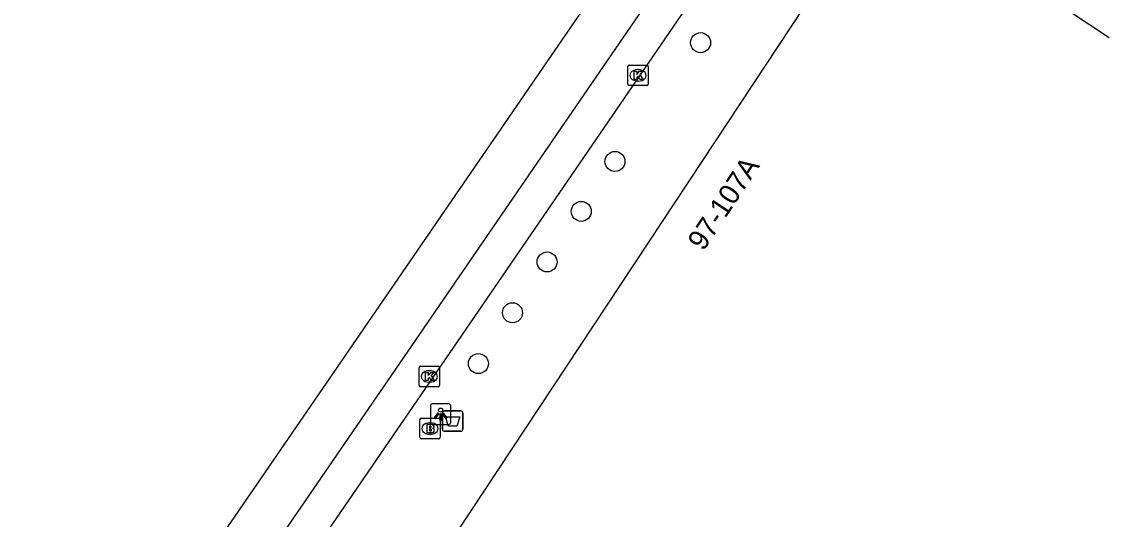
# Model space of a CAD drawing. Extents: x 160356 to 161355, y 381727 to 382845.
# Drawn here: x 160764.7 to 160817.9, y 382583 to 382607.3 of the extents above; entities that cross this region are included whole.
import ezdxf

# ---------------------------------------------------------------- set-up
doc = ezdxf.new("R2010")
doc.units = 0
for name, color, linetype in [('IMGEO_Afvalbak', 7, 'Continuous'), ('IMGEO_Boom', 7, 'Continuous'), ('IMGEO_Brandkraan', 7, 'Continuous'), ('IMGEO_Kolk', 7, 'Continuous'), ('IMGEO_Lichtpunt', 7, 'Continuous'), ('IMGEO_Pand', 7, 'Continuous'), ('IMGEO_Pand_nummerreeks', 7, 'Continuous'), ('IMGEO_Rijbaan_lokaal_gesloten', 7, 'Continuous')]:
    doc.layers.add(name, color=color, linetype=linetype)

msp = doc.modelspace()

# ---------------------------------------------------------------- linework, layer by layer
at = {"layer": 'IMGEO_Afvalbak'}
for p, q in [((160785.325, 382587.366), (160785.325, 382588.166)), ((160785.325, 382588.166), (160785.325, 382587.366)), ((160785.425, 382588.266), (160786.215, 382588.266)), ((160786.215, 382588.266), (160785.425, 382588.266)), ((160786.315, 382588.166), (160786.315, 382587.366)), ((160786.315, 382587.366), (160786.315, 382588.166)), ((160786.215, 382587.266), (160785.425, 382587.266)), ((160785.425, 382587.266), (160786.215, 382587.266))]:
    msp.add_line(p, q, dxfattribs=at)
msp.add_lwpolyline([(160785.468, 382587.98), (160786.172, 382587.98), (160786.023, 382587.51), (160785.617, 382587.51), (160785.468, 382587.98)], dxfattribs=at)
for centre, start, end in [((160785.425, 382588.166), 90, 180), ((160785.425, 382588.166), 90, 180), ((160786.215, 382588.166), 0, 90), ((160786.215, 382588.166), 360, 90), ((160785.425, 382587.366), 180, 270), ((160785.425, 382587.366), 180, 270), ((160786.215, 382587.366), 270, 0), ((160786.215, 382587.366), 270, 0)]:
    msp.add_arc(centre, 0.1, start, end, dxfattribs=at)
at = {"layer": 'IMGEO_Boom'}
for centre in [(160797.947, 382606.26), (160793.762, 382600.455), (160792.113, 382598.016), (160790.44, 382595.542), (160788.749, 382593.06), (160787.081, 382590.575)]:
    msp.add_circle(centre, 0.489, dxfattribs=at)
at = {"layer": 'IMGEO_Brandkraan'}
for p, q in [((160784.214, 382586.975), (160784.214, 382587.827)), ((160784.289, 382587.901), (160785.141, 382587.901)), ((160785.215, 382587.827), (160785.215, 382586.975)), ((160784.702, 382587.681), (160784.727, 382587.681)), ((160785.141, 382586.901), (160784.289, 382586.901)), ((160784.725, 382587.121), (160784.7, 382587.121))]:
    msp.add_line(p, q, dxfattribs=at)
for points in [[(160784.214, 382586.975), (160784.214, 382587.827)], [(160784.289, 382587.901), (160785.141, 382587.901)], [(160785.215, 382587.827), (160785.215, 382586.975)], [(160784.562, 382587.601), (160784.562, 382587.201), (160784.775, 382587.201)], [(160784.793, 382587.601), (160784.562, 382587.601)], [(160784.741, 382587.52), (160784.687, 382587.52), (160784.687, 382587.444)], [(160784.687, 382587.444), (160784.74, 382587.444)], [(160784.749, 382587.368), (160784.687, 382587.368), (160784.687, 382587.287)], [(160784.687, 382587.287), (160784.749, 382587.287)], [(160785.141, 382586.901), (160784.289, 382586.901)]]:
    msp.add_lwpolyline(points, dxfattribs=at)
for centre, radius, start, end in [((160784.291, 382587.825), 0.0765, 91.552, 178.448), ((160784.291, 382587.825), 0.0765, 91.552, 178.448), ((160785.139, 382587.825), 0.0765, 1.552, 88.448), ((160785.139, 382587.825), 0.0765, 1.552, 88.448), ((160784.742, 382587.482), 0.0379, 267.8285, 90.9355), ((160784.75, 382587.327), 0.0404, 269.8759, 90.5077), ((160784.797, 382587.456), 0.145, 59.4692, 91.5367), ((160784.822, 382587.503), 0.0922, 285.5137, 58.1501), ((160784.827, 382587.311), 0.105, 301.3115, 78.989), ((160784.291, 382586.977), 0.0765, 181.552, 268.448), ((160784.291, 382586.977), 0.0765, 181.552, 268.448), ((160784.781, 382587.452), 0.251, 268.6676, 293.5347), ((160785.139, 382586.977), 0.0765, 271.552, 358.448), ((160785.139, 382586.977), 0.0765, 271.552, 358.448)]:
    msp.add_arc(centre, radius, start, end, dxfattribs=at)
for centre, major_axis, ratio, start_param, end_param in [((160784.701, 382587.401), (-0.387, 0.002), 0.722429, 4.712389, 7.853982), ((160784.726, 382587.401), (-0.39, 0.002), 0.717154, 1.570796, 4.712389)]:
    msp.add_ellipse(centre, major_axis=major_axis, ratio=ratio, start_param=start_param, end_param=end_param, dxfattribs=at)
at = {"layer": 'IMGEO_Kolk'}
for p, q in [((160794.385, 382604.236), (160794.385, 382605.088)), ((160794.46, 382605.162), (160795.312, 382605.162)), ((160794.873, 382604.942), (160794.898, 382604.942)), ((160795.386, 382605.088), (160795.386, 382604.236)), ((160794.896, 382604.382), (160794.871, 382604.382)), ((160795.312, 382604.162), (160794.46, 382604.162)), ((160784.255, 382590.447), (160785.107, 382590.447)), ((160784.18, 382589.521), (160784.18, 382590.373)), ((160784.668, 382590.227), (160784.693, 382590.227)), ((160785.181, 382590.373), (160785.181, 382589.521)), ((160785.107, 382589.447), (160784.255, 382589.447)), ((160784.691, 382589.667), (160784.666, 382589.667))]:
    msp.add_line(p, q, dxfattribs=at)
for points in [[(160794.385, 382604.236), (160794.385, 382605.088)], [(160794.46, 382605.162), (160795.312, 382605.162)], [(160794.706, 382604.862), (160794.829, 382604.862), (160794.829, 382604.711), (160794.959, 382604.862), (160795.123, 382604.862), (160794.977, 382604.711), (160795.13, 382604.462), (160794.978, 382604.462), (160794.893, 382604.626), (160794.829, 382604.559), (160794.829, 382604.462), (160794.706, 382604.462), (160794.706, 382604.862)], [(160795.386, 382605.088), (160795.386, 382604.236)], [(160795.312, 382604.162), (160794.46, 382604.162)], [(160784.255, 382590.447), (160785.107, 382590.447)], [(160784.18, 382589.521), (160784.18, 382590.373)], [(160784.501, 382590.147), (160784.624, 382590.147), (160784.624, 382589.996), (160784.754, 382590.147), (160784.918, 382590.147), (160784.772, 382589.996), (160784.925, 382589.747), (160784.773, 382589.747), (160784.688, 382589.911), (160784.624, 382589.844), (160784.624, 382589.747), (160784.501, 382589.747), (160784.501, 382590.147)], [(160785.181, 382590.373), (160785.181, 382589.521)], [(160785.107, 382589.447), (160784.255, 382589.447)]]:
    msp.add_lwpolyline(points, dxfattribs=at)
for centre, start, end in [((160794.462, 382605.086), 91.552, 178.448), ((160794.462, 382605.086), 91.552, 178.448), ((160795.31, 382605.086), 1.552, 88.448), ((160795.31, 382605.086), 1.552, 88.448), ((160794.462, 382604.238), 181.552, 268.448), ((160794.462, 382604.238), 181.552, 268.448), ((160795.31, 382604.238), 271.552, 358.448), ((160795.31, 382604.238), 271.552, 358.448), ((160784.257, 382590.371), 91.552, 178.448), ((160784.257, 382590.371), 91.552, 178.448), ((160785.105, 382590.371), 1.552, 88.448), ((160785.105, 382590.371), 1.552, 88.448), ((160784.257, 382589.523), 181.552, 268.448), ((160784.257, 382589.523), 181.552, 268.448), ((160785.105, 382589.523), 271.552, 358.448), ((160785.105, 382589.523), 271.552, 358.448)]:
    msp.add_arc(centre, 0.0765, start, end, dxfattribs=at)
for centre, major_axis, ratio, start_param, end_param in [((160794.872, 382604.662), (-0.387, 0.002), 0.722429, 4.712389, 7.853982), ((160794.897, 382604.662), (-0.39, 0.002), 0.717154, 1.570796, 4.712389), ((160784.667, 382589.947), (-0.387, 0.002), 0.722429, 4.712389, 7.853982), ((160784.692, 382589.947), (-0.39, 0.002), 0.717154, 1.570796, 4.712389)]:
    msp.add_ellipse(centre, major_axis=major_axis, ratio=ratio, start_param=start_param, end_param=end_param, dxfattribs=at)
at = {"layer": 'IMGEO_Lichtpunt'}
for p, q in [((160784.733, 382588.508), (160784.733, 382587.701)), ((160784.733, 382588.508), (160784.733, 382587.701)), ((160785.635, 382588.603), (160784.827, 382588.603)), ((160785.635, 382588.603), (160784.827, 382588.603)), ((160785.729, 382587.701), (160785.729, 382588.508)), ((160785.729, 382587.701), (160785.729, 382588.508)), ((160784.827, 382587.607), (160785.635, 382587.607)), ((160784.827, 382587.607), (160785.635, 382587.607))]:
    msp.add_line(p, q, dxfattribs=at)
for points in [[(160785.107, 382588.172), (160785.146, 382588.144), (160784.958, 382587.882), (160784.92, 382587.909), (160785.107, 382588.172)], [(160785.209, 382588.124), (160785.256, 382588.124), (160785.256, 382587.802), (160785.209, 382587.802), (160785.209, 382588.124)], [(160785.319, 382588.144), (160785.357, 382588.171), (160785.544, 382587.909), (160785.505, 382587.881), (160785.319, 382588.144)]]:
    msp.add_lwpolyline(points, dxfattribs=at)
msp.add_circle((160785.232, 382588.306), 0.0994, dxfattribs=at)
for centre, start, end in [((160784.827, 382588.508), 90, 180), ((160784.827, 382588.508), 90, 180), ((160785.635, 382588.508), 0, 90), ((160785.635, 382588.508), 0, 90), ((160784.827, 382587.701), 180, 270), ((160784.827, 382587.701), 180, 270), ((160785.635, 382587.701), 270, 0), ((160785.635, 382587.701), 270, 360)]:
    msp.add_arc(centre, 0.0946, start, end, dxfattribs=at)
at = {"layer": 'IMGEO_Pand'}
for points in [[(160817.936, 382606.492), (160806.866, 382613.823)], [(160802.971, 382607.941), (160797.407, 382599.539), (160786.003, 382582.317)]]:
    msp.add_lwpolyline(points, dxfattribs=at)
at = {"layer": 'IMGEO_Rijbaan_lokaal_gesloten'}
for points in [[(160764.748, 382567.942), (160796.589, 382614.286)], [(160798.571, 382612.945), (160766.747, 382566.578)], [(160768.188, 382565.595), (160799.205, 382610.813)]]:
    msp.add_lwpolyline(points, dxfattribs=at)

# ---------------------------------------------------------------- texts
at = {"layer": 'IMGEO_Pand_nummerreeks'}
msp.add_text('97-107A', height=1, rotation=56.4879, dxfattribs=at).set_placement((160798.085, 382596.034))

doc.saveas('drawing.dxf')
